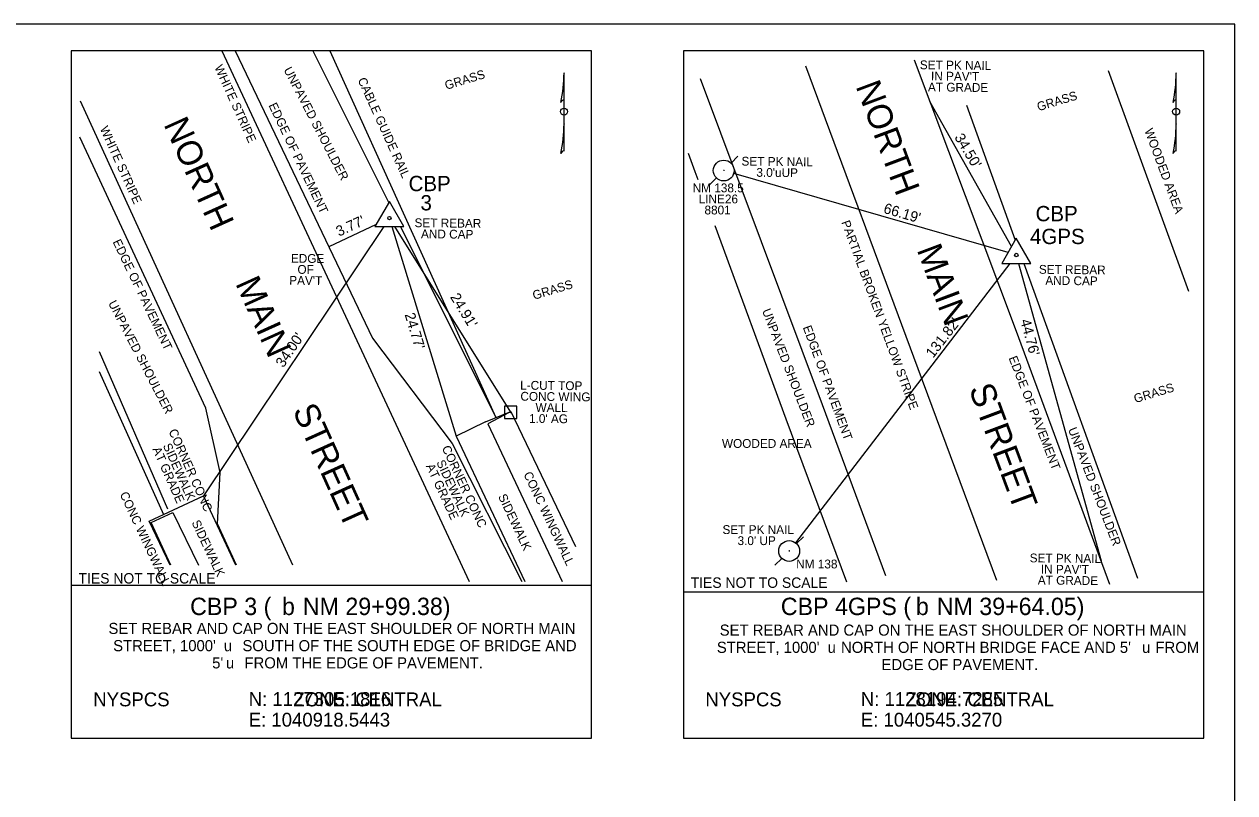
# Model space of a CAD drawing. Extents: x 1042984 to 1043775, y 1125614 to 1126116.
# Drawn here: x 1043379.9 to 1043775.4, y 1125865.1 to 1126116 of the extents above; entities that cross this region are included whole.
import ezdxf

# ---------------------------------------------------------------- set-up
doc = ezdxf.new("R2010")
doc.units = 0
for name, color, linetype in [('BDSW', 7, 'Continuous'), ('BWW', 7, 'Continuous'), ('BWW_C', 7, 'Continuous'), ('CB', 7, 'Continuous'), ('CBP', 7, 'Continuous'), ('CBP_C', 7, 'Continuous'), ('CBT', 7, 'Continuous'), ('CPBM', 7, 'Continuous'), ('Default', 7, 'Continuous'), ('LAWA', 7, 'Continuous'), ('LAWA_C', 7, 'Continuous'), ('LFNC_C', 7, 'Continuous'), ('LUKP_C', 7, 'Continuous'), ('NNA_P', 7, 'Continuous'), ('PE', 7, 'Continuous'), ('PE_C', 7, 'Continuous'), ('PSU_C', 7, 'Continuous'), ('RC_C', 7, 'Continuous'), ('RDU', 7, 'Continuous'), ('RGC', 7, 'Continuous'), ('RSW_C', 7, 'Continuous'), ('STPBY', 7, 'Continuous'), ('STPBY_C', 7, 'Continuous'), ('STSEW', 7, 'Continuous'), ('STSEW_I', 7, 'Continuous'), ('UP', 7, 'Continuous'), ('UP_C', 7, 'Continuous')]:
    doc.layers.add(name, color=color, linetype=linetype)

# ---------------------------------------------------------------- blocks, each defined once
blk = doc.blocks.new('NNAM')
at = {"layer": 'NNA_P'}
for p, q in [((0, 0.0147), (0, 0.0501)), ((0, 0.0496), (0, 0.0496)), ((0, 0.0496), (0, 0.0496)), ((0, -0.0004), (0, 0.0147)), ((0, -0.0168), (0, -0.0004)), ((0, -0.0166), (0, -0.0168)), ((0, -0.0172), (0, -0.0168)), ((0, -0.0518), (0, -0.0172))]:
    blk.add_line(p, q, dxfattribs=at)
blk.add_circle((0, -0.0003), 0.00455, dxfattribs=at)
for centre, radius, start, end in [((-0.1834, 0.0501), 0.1834, 347.8839, 359.8678), ((0.1834, 0.0501), 0.1834, 179.9909, 180.1322), ((0, 0.0105), 0.00425, 90.435, 165.5809), ((-0.1834, -0.0164), 0.1834, 347.8839, 359.8678), ((0.1834, -0.0164), 0.1834, 179.9909, 180.1322), ((-0.1834, -0.0164), 0.1834, 359.9196, 0.009), ((0, -0.056), 0.00424, 90.0107, 164.1061)]:
    blk.add_arc(centre, radius, start, end, dxfattribs=at)

msp = doc.modelspace()

# ---------------------------------------------------------------- linework, layer by layer
at = {"layer": 'BDSW'}
for points in [[(1043530.57, 1125986.26), (1043521.07, 1125981.53), (1043543.48, 1125934.13)], [(1043449.06, 1125939.48), (1043438.49, 1125962.06)]]:
    msp.add_lwpolyline(points, dxfattribs=at)
at = {"layer": 'BWW'}
for points in [[(1043530.57, 1125986.26), (1043538.89, 1125989.66), (1043560.03, 1125945.51)], [(1043538.34, 1125989.29), (1043531.37, 1125985.6), (1043555.69, 1125934.13)], [(1043428.69, 1125957.51), (1043438.49, 1125962.06)], [(1043427.62, 1125939.48), (1043420.75, 1125953.79), (1043428.69, 1125957.51)], [(1043427.84, 1125939.48), (1043421.42, 1125953.36), (1043428.41, 1125956.63)], [(1043428.41, 1125956.63), (1043436.78, 1125939.48)]]:
    msp.add_lwpolyline(points, dxfattribs=at)
at = {"layer": 'CB'}
for p, q in [((1043395.27, 1125932.94), (1043565.27, 1125932.94)), ((1043595.27, 1125930.74), (1043765.27, 1125930.74))]:
    msp.add_line(p, q, dxfattribs=at)
for points in [[(1042984.33, 1125614.24), (1043775.43, 1125614.24), (1043775.43, 1126116.03), (1042984.33, 1126116.03)], [(1043565.27, 1125882.94), (1043565.27, 1126107.4), (1043395.27, 1126107.4), (1043395.27, 1125882.94)], [(1043765.27, 1125882.94), (1043765.27, 1126107.4), (1043595.27, 1126107.4), (1043595.27, 1125882.94)]]:
    msp.add_lwpolyline(points, close=True, dxfattribs=at)
at = {"layer": 'CBP'}
for points in [[(1043499.22, 1126058.19), (1043494.49, 1126050.01)], [(1043503.94, 1126050.01), (1043499.22, 1126058.19)], [(1043494.49, 1126050.01), (1043503.94, 1126050.01)], [(1043704.04, 1126046.15), (1043699.32, 1126037.97)], [(1043708.77, 1126037.97), (1043704.04, 1126046.15)], [(1043699.32, 1126037.97), (1043708.77, 1126037.97)]]:
    msp.add_lwpolyline(points, dxfattribs=at)
for centre in [(1043499.22, 1126052.74), (1043704.04, 1126040.69)]:
    msp.add_circle(centre, 0.564, dxfattribs=at)
at = {"layer": 'CBT'}
for p, q in [((1043702.49, 1126043.45), (1043675.79, 1126090.79)), ((1043701.34, 1126041.47), (1043611.72, 1126067.33)), ((1043497.39, 1126050.01), (1043438.49, 1125962.06)), ((1043494.87, 1126050.67), (1043479.46, 1126043.34)), ((1043500.05, 1126050.01), (1043521.07, 1125981.53)), ((1043500.92, 1126050.01), (1043538.79, 1125989.36)), ((1043701.95, 1126037.97), (1043631.9, 1125946.77)), ((1043704.8, 1126037.97), (1043731.74, 1125940.87))]:
    msp.add_line(p, q, dxfattribs=at)
at = {"layer": 'CPBM'}
msp.add_lwpolyline([(1043536.79, 1125987.36), (1043540.8, 1125987.36), (1043540.8, 1125991.36), (1043536.79, 1125991.36)], close=True, dxfattribs=at)
for points in [[(1043538.68, 1125989.24), (1043538.91, 1125989.48)], [(1043538.68, 1125989.48), (1043538.91, 1125989.24)], [(1043538.79, 1125989.36), (1043538.79, 1125989.36)]]:
    msp.add_lwpolyline(points, dxfattribs=at)
msp.add_circle((1043538.79, 1125989.36), 0.165, dxfattribs=at)
at = {"layer": 'LAWA'}
msp.add_lwpolyline([(1043760.43, 1126028.75), (1043734.12, 1126100.79)], dxfattribs=at)
at = {"layer": 'PE'}
for points in [[(1043448.86, 1126107.4), (1043493.7, 1126013.53), (1043519.67, 1125979.16), (1043542.49, 1125934.13)], [(1043670.68, 1126104.39), (1043704.02, 1126015.79), (1043734.5, 1125933.27)], [(1043661.43, 1125936), (1043640.73, 1125991.8), (1043600.81, 1126098.26)], [(1043449.28, 1125939.48), (1043442.99, 1125952.95), (1043443.87, 1125969.65), (1043439.26, 1125990.65), (1043398.1, 1126079.13)]]:
    msp.add_lwpolyline(points, dxfattribs=at)
at = {"layer": 'RDU'}
for points in [[(1043474.18, 1126107.4), (1043498.97, 1126057.76)], [(1043687.79, 1126089.57), (1043703.71, 1126045.57)], [(1043600.1, 1126065.26), (1043599.14, 1126067.83), (1043596.91, 1126073.81)], [(1043502.84, 1126050.01), (1043533.96, 1125987.7)], [(1043648.66, 1125933.86), (1043628.9, 1125987.06), (1043605.68, 1126050.27)], [(1043706.46, 1126037.97), (1043743.62, 1125935.23)], [(1043426.81, 1125957.77), (1043404.52, 1126009.13)]]:
    msp.add_lwpolyline(points, dxfattribs=at)
at = {"layer": 'RGC'}
for points in [[(1043479.79, 1126107.4), (1043533.96, 1125987.7)], [(1043425.54, 1125955.89), (1043404.52, 1126002.54)]]:
    msp.add_lwpolyline(points, dxfattribs=at)
at = {"layer": 'STPBY'}
msp.add_lwpolyline([(1043697.73, 1125934.38), (1043672.01, 1126003.5), (1043635.27, 1126102.37)], dxfattribs=at)
at = {"layer": 'STSEW'}
for points in [[(1043444.43, 1126107.4), (1043525.3, 1125934.13)], [(1043467.64, 1125939.48), (1043398.32, 1126090.97)]]:
    msp.add_lwpolyline(points, dxfattribs=at)
at = {"layer": 'UP'}
for p, q in [((1043610.84, 1126070.69), (1043613.09, 1126072.95)), ((1043606.05, 1126065.86), (1043603.8, 1126063.59)), ((1043608.56, 1126068.27), (1043608.33, 1126068.27)), ((1043608.45, 1126068.38), (1043608.45, 1126068.16)), ((1043632.23, 1125946.48), (1043634.47, 1125948.74)), ((1043629.94, 1125944.07), (1043629.72, 1125944.07)), ((1043629.83, 1125944.18), (1043629.83, 1125943.95)), ((1043627.43, 1125941.65), (1043625.18, 1125939.39))]:
    msp.add_line(p, q, dxfattribs=at)
for centre in [(1043608.45, 1126068.27), (1043629.83, 1125944.07)]:
    msp.add_circle(centre, 3.4, dxfattribs=at)

# ---------------------------------------------------------------- block references
at = {"layer": 'Default', "xscale": 250, "yscale": 250}
for p in [(1043556.27, 1126087.59), (1043756.27, 1126087.59)]:
    msp.add_blockref('NNAM', p, dxfattribs=at)

# ---------------------------------------------------------------- texts
at = {"layer": 'BWW_C'}
for p in [(1043542.95, 1125969.15), (1043411.01, 1125962.61)]:
    msp.add_text('CONC WINGWALL', height=2.88, rotation=295.1926, dxfattribs=at).set_placement(p)
at = {"layer": 'CBP_C'}
for s, height, rotation, p in [("34.50'", 3.402, 300.9365, (1043683.7, 1126079.13)), ("66.19'", 3.402, 343.8266, (1043660.43, 1126054.48)), ("3.77'", 3.402, 24.5284, (1043482.7, 1126046.65)), ("24.91'", 3.402, 301.378, (1043518.94, 1126026.98)), ("24.77'", 3.402, 286.8239, (1043504.15, 1126021.29)), ("131.82'", 3.402, 52.3104, (1043676.86, 1126006.84)), ("44.76'", 3.402, 285.1785, (1043705.33, 1126019.3)), ("34.00'", 3.402, 55.8368, (1043464.56, 1126003.7)), ('TIES NOT TO SCALE', 3.4016, 359.9999, (1043397.64, 1125933.45)), ('TIES NOT TO SCALE', 3.4016, 359.9999, (1043597.64, 1125932.03))]:
    msp.add_text(s, height=height, rotation=rotation, dxfattribs=at).set_placement(p)
for s, height, p in [('CBP', 5.002, (1043505.48, 1126061.53)), ('3', 5, (1043509.37, 1126055.26)), ('CBP ', 5.002, (1043710.35, 1126051.7)), ('4GPS', 5.002, (1043708.53, 1126044.26)), ('CBP 3 (', 5.669, (1043434.09, 1125923.15)), ('b', 5.67, (1043464.11, 1125923.15)), (' NM 29+99.38)', 5.6693, (1043468.82, 1125923.15)), ('CBP 4GPS (', 5.669, (1043627.11, 1125923.15)), ('b', 5.67, (1043671.24, 1125923.15)), (' NM 39+64.05)', 5.6693, (1043675.95, 1125923.15)), ('SET REBAR AND CAP ON THE EAST SHOULDER OF NORTH MAIN', 3.6284, (1043407.41, 1125916.98)), ('SET REBAR AND CAP ON THE EAST SHOULDER OF NORTH MAIN', 3.6284, (1043607.13, 1125916.43)), ("STREET, 1000'", 3.6284, (1043408.95, 1125911.35)), ('SOUTH OF THE SOUTH EDGE OF BRIDGE AND', 3.6284, (1043451.2, 1125911.35)), ('u ', 3.628, (1043445.12, 1125911.35)), ("STREET, 1000'", 3.6284, (1043606.2, 1125910.8)), ('u', 3.63, (1043642.38, 1125910.8)), (" NORTH OF NORTH BRIDGE FACE AND 5'", 3.6284, (1043645.42, 1125910.8)), ('u', 3.63, (1043745.13, 1125910.8)), (' FROM', 3.628, (1043748.17, 1125910.8)), ("5'", 3.628, (1043441.3, 1125905.73)), ('u ', 3.628, (1043445.79, 1125905.73)), ('FROM THE EDGE OF PAVEMENT.', 3.6284, (1043451.86, 1125905.73)), ('EDGE OF PAVEMENT.', 3.6284, (1043659.99, 1125905.18)), ('NYSPCS                        ZONE: CENTRAL', 4.5355, (1043402.44, 1125893.35)), ('N: 1127305.1816', 4.5355, (1043453.23, 1125893.47)), ('NYSPCS                        ZONE: CENTRAL', 4.5355, (1043602.44, 1125893.35)), ('N: 1128194.7285', 4.5355, (1043653.23, 1125893.47)), ('E: 1040918.5443', 4.5355, (1043453.23, 1125886.72)), ('E: 1040545.3270', 4.5355, (1043653.23, 1125886.72))]:
    msp.add_text(s, height=height, dxfattribs=at).set_placement(p)
at = {"layer": 'LAWA_C'}
msp.add_text('WOODED AREA', height=2.88, rotation=290.3885, dxfattribs=at).set_placement((1043745.86, 1126081.38))
msp.add_text('WOODED AREA', height=2.88, dxfattribs=at).set_placement((1043607.86, 1125977.73))
at = {"layer": 'LFNC_C'}
for s, rotation, p in [('SET PK NAIL', 359.4406, (1043672.52, 1126101.34)), ('AT GRADE', 359.4406, (1043675.17, 1126094.1)), ("IN PAV'T", 359.4406, (1043676.16, 1126097.7)), ('SET PK NAIL', 359.4406, (1043614.25, 1126069.89)), ("3.0'uUP", 359.4406, (1043619.11, 1126066.24)), ('SET REBAR', 359.4406, (1043507.4, 1126049.79)), ('AND CAP', 359.4406, (1043509.52, 1126046.16)), ('EDGE', 359.4406, (1043467.01, 1126038.19)), ("PAV'T", 359.4406, (1043466.46, 1126030.99)), ('OF', 359.4406, (1043469.15, 1126034.57)), ('SET REBAR', 359.4406, (1043711.4, 1126034.58)), ('AND CAP', 359.4406, (1043713.52, 1126030.96)), ('L-CUT TOP', 359.4406, (1043541.92, 1125996.75)), ('CONC WING', 359.4406, (1043542, 1125993.14)), ('WALL', 359.4406, (1043546.94, 1125989.49)), ("1.0' AG", 359.4406, (1043544.82, 1125985.9)), ('CORNER CONC', 294.1469, (1043426.99, 1125983.15)), ('SIDEWALK', 294.1469, (1043425.14, 1125978.47)), ('CORNER CONC', 294.9666, (1043516.26, 1125977.71)), ('AT GRADE', 294.1469, (1043421.71, 1125977.31)), ('AT GRADE', 294.9666, (1043511.07, 1125971.79)), ('SIDEWALK', 294.9666, (1043514.48, 1125973)), ('SET PK NAIL', 359.4406, (1043708.41, 1125940.36)), ("IN PAV'T", 359.4406, (1043712.06, 1125936.72)), ('AT GRADE', 359.4406, (1043711.06, 1125933.13))]:
    msp.add_text(s, height=2.88, rotation=rotation, dxfattribs=at).set_placement(p)
for s, p in [('SET PK NAIL', (1043608.05, 1125949.61)), ("3.0' UP", (1043612.96, 1125946))]:
    msp.add_text(s, height=2.88, dxfattribs=at).set_placement(p)
at = {"layer": 'LUKP_C'}
for p in [(1043517.8, 1126094.59), (1043711.31, 1126087.62), (1043546.49, 1126026.04), (1043742.95, 1125992.33)]:
    msp.add_text('GRASS', height=2.88, rotation=16.8553, dxfattribs=at).set_placement(p)
at = {"layer": 'PE_C'}
for s, rotation, p in [('CABLE GUIDE RAIL', 294.4432, (1043488.77, 1126097.86)), ('EDGE OF PAVEMENT', 295.585, (1043459.64, 1126089.57)), ('EDGE OF PAVEMENT', 295.585, (1043408.72, 1126045)), ('EDGE OF PAVEMENT', 290.1716, (1043634.25, 1126017.09)), ('EDGE OF PAVEMENT', 291.3238, (1043701.48, 1126007.08))]:
    msp.add_text(s, height=2.88, rotation=rotation, dxfattribs=at).set_placement(p)
at = {"layer": 'PSU_C'}
for rotation, p in [(297.4345, (1043464.57, 1126101.18)), (297.4345, (1043407.25, 1126024.96)), (291.1011, (1043620.93, 1126022.53)), (291.1011, (1043720.91, 1125983.77))]:
    msp.add_text('UNPAVED SHOULDER', height=2.88, rotation=rotation, dxfattribs=at).set_placement(p)
at = {"layer": 'RC_C'}
for s, rotation, p in [('NORTH      MAIN       STREET', 290.5151, (1043651.48, 1126095.8)), ('NORTH      MAIN      STREET', 294.2836, (1043425.32, 1126083.37))]:
    msp.add_text(s, height=8.16, rotation=rotation, dxfattribs=at).set_placement(p)
at = {"layer": 'RSW_C'}
for p in [(1043534.66, 1125961.9), (1043434.51, 1125953.36)]:
    msp.add_text('SIDEWALK', height=2.88, rotation=295.1926, dxfattribs=at).set_placement(p)
at = {"layer": 'STPBY_C'}
msp.add_text('PARTIAL BROKEN YELLOW STRIPE', height=2.88, rotation=290.177, dxfattribs=at).set_placement((1043646.83, 1126051.39))
at = {"layer": 'STSEW_I'}
for p in [(1043441.96, 1126102), (1043404.54, 1126081.98)]:
    msp.add_text('WHITE STRIPE', height=2.88, rotation=294.2778, dxfattribs=at).set_placement(p)
at = {"layer": 'UP_C'}
for s, p in [('NM 138.5', (1043598.3, 1126061.16)), ('LINE26', (1043600.27, 1126057.55)), ('8801', (1043602.16, 1126053.94)), ('NM 138', (1043632.13, 1125938.38))]:
    msp.add_text(s, height=2.88, dxfattribs=at).set_placement(p)

doc.saveas('drawing.dxf')
